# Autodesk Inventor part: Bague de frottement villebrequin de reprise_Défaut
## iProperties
Shininess: 64.0
Length Units: 11269
Angle Units: 11279
Time Units: 11290
Mass Units: 11283
Length Display Precision: 3
Angle Display Precision: 2
Compacted: True
Part Number: Bague de frottement villebrequin de reprise_Défaut
Document SubType Name: Modeling
Created: 2006-01
Material: Par défaut
Designer: riri
Density: 0.0
Volumn: 0.0
Area: 0.0
PropertySet Name: Model Information
Control State: 0
Master: False
Checked Out: False
Author: riri
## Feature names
1. Base1
